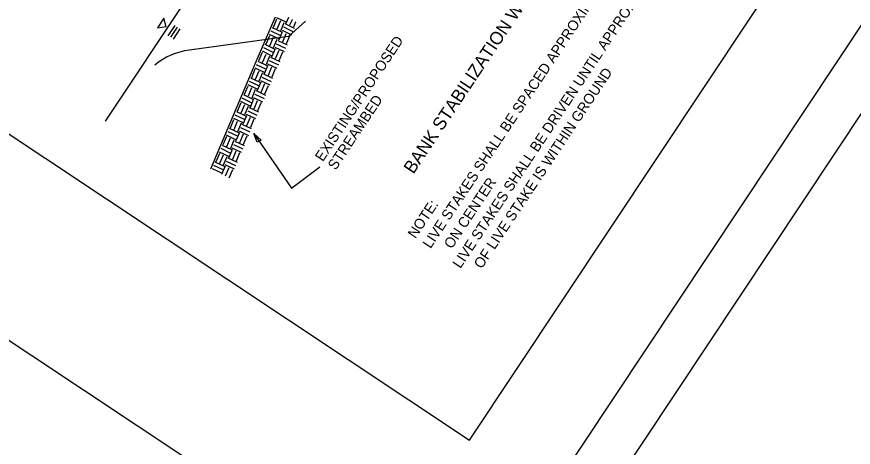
# Model space of a CAD drawing. Extents: x 561231 to 564935, y 589159 to 602519.
# Drawn here: x 564299.4 to 564529.6, y 589301.4 to 589419.8 of the extents above; entities that cross this region are included whole.
import ezdxf

# ---------------------------------------------------------------- set-up
doc = ezdxf.new("R2010")
doc.units = 0
doc.layers.add('Old_Level_1', color=7, linetype='Continuous')
doc.layers.add('Sheet Plot Border Outside CELL', color=7, linetype='Continuous')

msp = doc.modelspace()

# ---------------------------------------------------------------- linework, layer by layer
at = {"layer": 'Old_Level_1'}
for p, q in [((564362.22, 589449.01), (564323.73, 589391.1)), ((564370.58, 589419.75), (564365.22, 589407.43)), ((564370.91, 589419.64), (564373.47, 589418.41)), ((564341.14, 589414.63), (564343.03, 589417.46)), ((564341.82, 589414.18), (564343.69, 589417.01)), ((564342.54, 589413.71), (564344.42, 589416.53)), ((564369.72, 589416.88), (564372.26, 589415.66)), ((564372.83, 589417.02), (564375.38, 589415.8)), ((564373.24, 589417.94), (564375.78, 589416.72)), ((564368.92, 589415.04), (564371.46, 589413.81)), ((564369.32, 589415.96), (564371.86, 589414.74)), ((564372.45, 589416.12), (564375, 589414.88)), ((564367.71, 589412.28), (564370.27, 589411.04)), ((564370.84, 589412.42), (564373.39, 589411.2)), ((564371.25, 589413.35), (564373.81, 589412.11)), ((564366.92, 589410.44), (564369.47, 589409.22)), ((564367.33, 589411.35), (564369.88, 589410.11)), ((564370.44, 589411.5), (564373.01, 589410.26)), ((564365.22, 589407.43), (564352.79, 589377.93)), ((564365.73, 589407.66), (564368.28, 589406.44)), ((564368.87, 589407.81), (564371.41, 589406.58)), ((564369.25, 589408.73), (564371.81, 589407.51)), ((564364.95, 589405.82), (564367.51, 589404.62)), ((564365.32, 589406.74), (564367.89, 589405.54)), ((564368.45, 589406.9), (564371.01, 589405.68)), ((564363.78, 589403.05), (564366.33, 589401.84)), ((564366.89, 589403.23), (564369.46, 589402)), ((564367.29, 589404.14), (564369.85, 589402.92)), ((564362.98, 589401.2), (564365.53, 589399.99)), ((564363.38, 589402.13), (564365.93, 589400.92)), ((564366.5, 589402.29), (564369.07, 589401.07)), ((564361.81, 589398.42), (564364.36, 589397.21)), ((564364.92, 589398.59), (564367.49, 589397.39)), ((564365.33, 589399.52), (564367.87, 589398.3)), ((564361.02, 589396.59), (564363.59, 589395.37)), ((564361.41, 589397.5), (564363.98, 589396.29)), ((564364.55, 589397.67), (564367.09, 589396.47)), ((564359.86, 589393.8), (564362.4, 589392.6)), ((564362.98, 589393.96), (564365.53, 589392.76)), ((564363.36, 589394.89), (564365.92, 589393.7)), ((564359.07, 589391.97), (564361.61, 589390.75)), ((564359.46, 589392.88), (564362.01, 589391.67)), ((564362.57, 589393.04), (564365.13, 589391.83)), ((564357.89, 589389.19), (564360.45, 589387.96)), ((564361, 589389.36), (564363.56, 589388.14)), ((564361.4, 589390.27), (564363.97, 589389.07)), ((564357.1, 589387.35), (564359.66, 589386.12)), ((564357.5, 589388.27), (564360.07, 589387.04)), ((564360.63, 589388.43), (564363.18, 589387.22)), ((564355.92, 589384.56), (564358.49, 589383.35)), ((564359.06, 589384.73), (564361.61, 589383.52)), ((564359.44, 589385.65), (564361.99, 589384.45)), ((564355.16, 589382.72), (564357.71, 589381.51)), ((564355.55, 589383.65), (564358.1, 589382.44)), ((564358.66, 589383.83), (564361.23, 589382.6)), ((564353.98, 589379.94), (564356.54, 589378.73)), ((564357.09, 589380.12), (564359.64, 589378.9)), ((564357.48, 589381.04), (564360.04, 589379.82)), ((564353.19, 589378.09), (564355.73, 589376.87)), ((564353.57, 589379.02), (564356.14, 589377.81)), ((564356.69, 589379.19), (564359.26, 589377.97))]:
    msp.add_line(p, q, dxfattribs=at)
for points in [[(564393.35, 590347.54), (563895.29, 589597.92), (564420.03, 589249.27), (564918.09, 589998.9)], [(564424.04, 589303.41), (564527.25, 589458.73), (564344.07, 589580.44), (564240.86, 589425.13)], [(564365.6, 589385.31), (564364.63, 589387.77), (564366.65, 589385.89)]]:
    msp.add_lwpolyline(points, close=True, dxfattribs=at)
for points in [[(564340.56, 589417.02), (564339.91, 589419.45), (564338.14, 589416.78), (564340.53, 589417.11)], [(564378.84, 589418.6), (564374.21, 589414.39), (564346.96, 589410.69)], [(564370.04, 589416.98), (564371.03, 589419.28)], [(564371.06, 589416.49), (564372.07, 589418.8)], [(564373.6, 589418.05), (564374.28, 589419.68), (564374.32, 589419.71)], [(564374.61, 589417.57), (564375.27, 589419.07), (564375.22, 589419)], [(564372.09, 589415.99), (564373.06, 589418.3)], [(564375.63, 589417.08), (564376.23, 589418.45), (564376.1, 589418.31)], [(564368.04, 589412.38), (564369.06, 589414.69)], [(564369.07, 589411.88), (564370.06, 589414.18)], [(564371.61, 589413.45), (564372.59, 589415.75)], [(564372.61, 589412.96), (564373.61, 589415.26)], [(564373.64, 589412.47), (564374.65, 589414.78)], [(564370.09, 589411.39), (564371.09, 589413.7)], [(564366.06, 589407.77), (564367.05, 589410.08)], [(564367.09, 589407.27), (564368.08, 589409.59)], [(564369.61, 589408.85), (564370.61, 589411.14)], [(564370.63, 589408.35), (564371.61, 589410.65)], [(564371.65, 589407.85), (564372.65, 589410.16)], [(564368.11, 589406.79), (564369.09, 589409.09)], [(564364.1, 589403.14), (564365.07, 589405.47)], [(564365.12, 589402.66), (564366.1, 589404.97)], [(564367.63, 589404.26), (564368.36, 589405.94), (564368.6, 589406.54)], [(564368.66, 589403.75), (564369.37, 589405.46), (564369.63, 589406.05)], [(564369.68, 589403.29), (564370.39, 589404.96), (564370.66, 589405.57)], [(564366.14, 589402.18), (564367.12, 589404.49)], [(564362.14, 589398.53), (564363.12, 589400.83)], [(564363.16, 589398.05), (564364.15, 589400.35)], [(564365.66, 589399.63), (564366.65, 589401.93)], [(564366.71, 589399.14), (564367.68, 589401.46)], [(564367.73, 589398.65), (564368.71, 589400.96)], [(564364.19, 589397.55), (564365.15, 589399.89)], [(564360.19, 589393.91), (564361.15, 589396.22)], [(564361.19, 589393.42), (564362.19, 589395.72)], [(564363.71, 589395.01), (564364.7, 589397.31)], [(564364.74, 589394.53), (564365.72, 589396.83)], [(564365.77, 589394.04), (564366.75, 589396.35)], [(564362.23, 589392.94), (564363.21, 589395.24)], [(564358.22, 589389.3), (564359.2, 589391.6)], [(564359.24, 589388.81), (564360.22, 589391.11)], [(564361.75, 589390.38), (564362.73, 589392.7)], [(564362.78, 589389.89), (564363.75, 589392.21)], [(564363.81, 589389.43), (564364.79, 589391.72)], [(564360.27, 589388.32), (564361.24, 589390.63)], [(564356.25, 589384.67), (564357.22, 589386.99)], [(564357.28, 589384.17), (564358.25, 589386.5)], [(564359.8, 589385.76), (564360.78, 589388.06)], [(564360.81, 589385.28), (564361.8, 589387.59)], [(564361.84, 589384.79), (564362.83, 589387.11)], [(564364.63, 589387.77), (564374.99, 589372.72), (564382.83, 589378.53)], [(564358.31, 589383.68), (564359.28, 589386)], [(564354.29, 589380.05), (564355.29, 589382.36)], [(564355.31, 589379.56), (564356.3, 589381.86)], [(564357.84, 589381.14), (564358.83, 589383.45)], [(564358.88, 589380.66), (564359.83, 589382.98)], [(564359.88, 589380.17), (564360.86, 589382.49)], [(564356.34, 589379.08), (564357.32, 589381.39)], [(564355.88, 589376.52), (564356.86, 589378.83)], [(564356.91, 589376.04), (564357.9, 589378.35)], [(564357.92, 589375.57), (564358.91, 589377.86)]]:
    msp.add_lwpolyline(points, dxfattribs=at)
msp.add_ellipse((564352.18, 589391.22), major_axis=(-17.82, 11.84), ratio=0.880425, start_param=5.497271, end_param=6.039087, dxfattribs=at)
at = {"layer": 'Sheet Plot Border Outside CELL'}
msp.add_lwpolyline([(564375.99, 589158.59), (564934.98, 589999.92), (564387.75, 590363.51), (563828.77, 589522.18)], close=True, dxfattribs=at)

# ---------------------------------------------------------------- texts
at = {"layer": 'Old_Level_1'}
for s, height, p in [('BANK STABILIZATION WITH LIVE STAKES', 3.5437, (564408.57, 589376.38)), ('LIVE STAKES SHALL BE SPACED APPROXIMATELY 4 FEET', 2.8393, (564413.26, 589355.89)), ('LIVE STAKES SHALL BE DRIVEN UNTIL APPROXIMATELY  3/4 ', 2.8393, (564421.49, 589350.42)), ('EXISTING/PROPOSED', 2.8393, (564383.65, 589379.81)), ('   OF LIVE STAKE IS WITHIN GROUND', 2.8393, (564425.6, 589347.69)), ('STREAMBED', 2.839, (564387.18, 589377.46)), ('   ON CENTER', 2.8393, (564417.38, 589353.16)), ('NOTE:', 2.839, (564409.15, 589358.63))]:
    msp.add_text(s, height=height, rotation=56.3664, dxfattribs=at).set_placement(p)

doc.saveas('drawing.dxf')
